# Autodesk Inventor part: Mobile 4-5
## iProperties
Author: Philippe
Shininess: 21.0
Angle Display Precision: 2
Document Length Units: 11269
Document Angle Units: 11283
Document Time Units: 11279
Document Mass Units: 11290
Document Length Units Precision: 3
Document Angle Units Precision: 2
Compacted: False
PropertySet Name: _Private Model Information
Created: 2002-01
Part Number: Mobile 4-5
Material: Par défaut
Document SubType Name: Modélisation
Designer: Philippe
Control State: 0
Master: False
Checked Out: False
PropertySet Name: Design Tracking Control
Density: 0.0
Volumn: 0.0
Area: 0.0
PropertySet Name: Model Information
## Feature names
1. Révolution1 [Revolution]
2. Extrusion1
3. Extrusion3
4. Réseau circulaire2 [Circular Pattern]
5. Extrusion4
6. Réseau circulaire3 [Circular Pattern]
